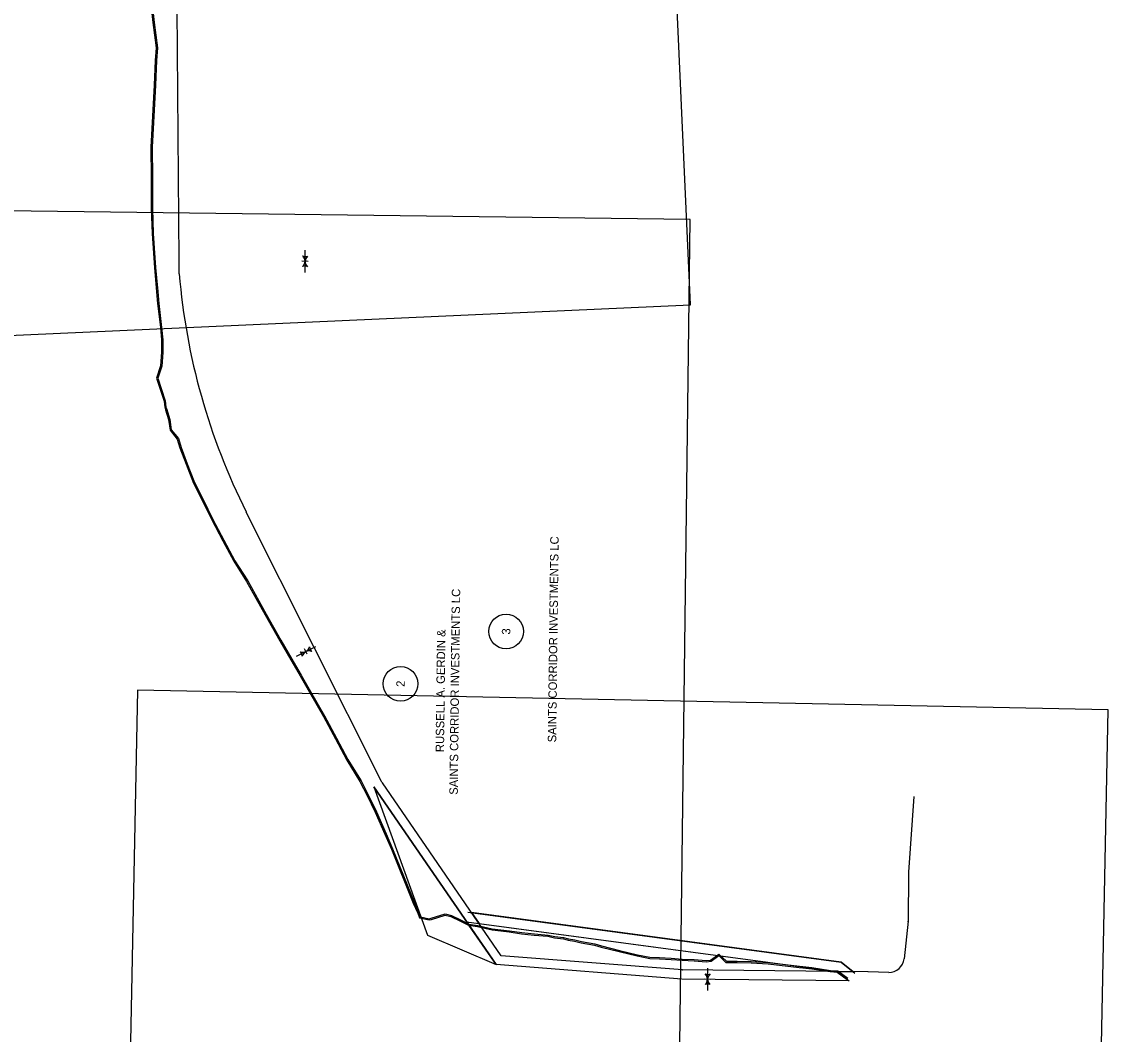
# Model space of a CAD drawing. Extents: x 20504422 to 20508365, y 7965199 to 7983597.
# Drawn here: x 20506611 to 20508365, y 7970508 to 7972142 of the extents above; entities that cross this region are included whole.
import ezdxf

# ---------------------------------------------------------------- set-up
doc = ezdxf.new("R2010")
doc.units = 0
for name, color, linetype in [('SurControl', 7, 'Continuous'), ('SurDikeDam', 7, 'Continuous'), ('SurHedge', 7, 'Continuous'), ('SurLotCorner', 7, 'Continuous'), ('SurRipRap', 7, 'Continuous'), ('SurTopOfWater', 7, 'Continuous'), ('SurTreeLineRight', 7, 'Continuous'), ('SurWetlands', 7, 'Continuous')]:
    doc.layers.add(name, color=color, linetype=linetype)

msp = doc.modelspace()

# ---------------------------------------------------------------- linework, layer by layer
at = {"layer": 'SurControl'}
for centre in [(20507392.5, 7971158.1), (20507222.2, 7971073.6)]:
    msp.add_circle(centre, 28, dxfattribs=at)
at = {"layer": 'SurDikeDam'}
for points in [[(20507179.2, 7970907.3), (20507265.7, 7970667.9), (20507376.4, 7970620.6)], [(20507336.9, 7970704.5), (20507348.9, 7970686.9), (20507927.3, 7970609.7), (20507927.3, 7970609.6), (20507952.3, 7970609.4), (20507933.4, 7970624.7)], [(20507328.9, 7970689.6), (20507927.3, 7970609.7), (20507946.2, 7970594.4), (20507676.2, 7970597.3), (20507376.4, 7970620.6)]]:
    msp.add_lwpolyline(points, close=True, dxfattribs=at)
at = {"layer": 'SurHedge'}
msp.add_lwpolyline([(20507336.9, 7970704.5), (20507348.9, 7970686.9), (20507927.3, 7970609.7), (20507927.3, 7970609.6), (20507952.3, 7970609.4), (20507933.4, 7970624.7)], close=True, dxfattribs=at)
at = {"layer": 'SurLotCorner'}
for p, q in [((20507068.1, 7971755.3), (20507068.3, 7971773.1)), ((20507073.1, 7971755.2), (20507063, 7971755.3)), ((20507068.1, 7971755.3), (20507067.9, 7971737.4)), ((20507069.5, 7971125.7), (20507053.5, 7971117.7)), ((20507071.7, 7971121.2), (20507067.2, 7971130.2)), ((20507069.5, 7971125.7), (20507085.4, 7971133.7)), ((20507717.8, 7970596.9), (20507718, 7970614.8)), ((20507722.8, 7970596.8), (20507712.7, 7970597)), ((20507717.8, 7970596.9), (20507717.5, 7970579))]:
    msp.add_line(p, q, dxfattribs=at)
for centre, radius, start, end in [((20507053.6, 7971757), 14.6, 315.366, 353.1732), ((20507053.6, 7971753.9), 14.6, 5.3849, 43.1922), ((20507068.3, 7971774.5), 11.4, 248.6722, 289.8859), ((20507082.6, 7971753.5), 14.6, 135.366, 173.1732), ((20507082.6, 7971756.6), 14.6, 185.3849, 223.1922), ((20507067.8, 7971736.1), 11.4, 68.6722, 109.8859), ((20507064.3, 7971139.3), 14.6, 252.7559, 290.5631), ((20507052.3, 7971117.1), 11.4, 6.0622, 47.2758), ((20507077.4, 7971113.4), 14.6, 122.7748, 160.5821), ((20507061.6, 7971138), 14.6, 302.7748, 340.5821), ((20507074.6, 7971112), 14.6, 72.7559, 110.5631), ((20507086.6, 7971134.3), 11.4, 186.0622, 227.2758), ((20507703.3, 7970598.6), 14.6, 315.366, 353.1732), ((20507703.2, 7970595.5), 14.6, 5.3849, 43.1922), ((20507718, 7970616.1), 11.4, 248.6722, 289.8859), ((20507732.3, 7970595.2), 14.6, 135.366, 173.1732), ((20507732.3, 7970598.3), 14.6, 185.3849, 223.1922), ((20507717.5, 7970577.7), 11.4, 68.6722, 109.8859)]:
    msp.add_arc(centre, radius, start, end, dxfattribs=at)
at = {"layer": 'SurRipRap'}
for points in [[(20505692.1, 7971595), (20507690.1, 7971685.2), (20507549.3, 7974806.4), (20505551.3, 7974716.3)], [(20505650.4, 7968713.3), (20507650.2, 7968688.1), (20507689.7, 7971822.9), (20505689.8, 7971848)]]:
    msp.add_lwpolyline(points, close=True, dxfattribs=at)
at = {"layer": 'SurTopOfWater'}
for points in [[(20506817.9, 7972179.4), (20506822.4, 7972140.4), (20506827.8, 7972099.9), (20506826.3, 7972079.5), (20506824.7, 7972039.5), (20506822.4, 7971999.5), (20506819.3, 7971939.7), (20506819.7, 7971889.8), (20506819.8, 7971839.9), (20506821.1, 7971800), (20506824.8, 7971745), (20506828.3, 7971706.2), (20506830, 7971687.1), (20506834.5, 7971648.4), (20506836.5, 7971628.7), (20506836.6, 7971608.5), (20506835, 7971586.4), (20506828.5, 7971566.5), (20506840.4, 7971529.7), (20506841.5, 7971519.9), (20506842.7, 7971515.6), (20506847.8, 7971499.9), (20506850.1, 7971482.6), (20506861.9, 7971468.3), (20506866.1, 7971454.4), (20506876, 7971428), (20506887.9, 7971397.6), (20506902.1, 7971369.9), (20506917.1, 7971339.1), (20506935.1, 7971304.5), (20506953.2, 7971271.3), (20506973.8, 7971238.7), (20507003.8, 7971184.8), (20507027.5, 7971142.8), (20507044.9, 7971112.4), (20507060.2, 7971086.4), (20507075.3, 7971060.3), (20507097.8, 7971020.9), (20507117, 7970985), (20507135.5, 7970950.3), (20507156.7, 7970916), (20507168.3, 7970893.5), (20507181.4, 7970866.3), (20507197, 7970831), (20507207.4, 7970806.6), (20507242.7, 7970719.5), (20507249.9, 7970703.5), (20507252.8, 7970696.1), (20507268.2, 7970692.6), (20507272.1, 7970693.6), (20507294.3, 7970700.3), (20507303.6, 7970698.1), (20507318.1, 7970691.1), (20507331.8, 7970684.1), (20507346.6, 7970681.9), (20507369.8, 7970676.5), (20507397.5, 7970673.3), (20507417.5, 7970670.5), (20507438, 7970668.1), (20507460, 7970666.3), (20507470.8, 7970664), (20507485, 7970662.4), (20507492.6, 7970660.1), (20507503.2, 7970658.5), (20507513.9, 7970655.9), (20507535.4, 7970652.1), (20507546.1, 7970649), (20507575.2, 7970641.5), (20507604.2, 7970634.7), (20507624.6, 7970630.5), (20507640.3, 7970629.8), (20507658.9, 7970628.9), (20507676.9, 7970627.6), (20507696.2, 7970626.8), (20507715.3, 7970625.1), (20507723.5, 7970625.9), (20507735.8, 7970635.1), (20507747.3, 7970623.9), (20507765.4, 7970624.2), (20507788, 7970623.4), (20507815.8, 7970622), (20507865.8, 7970615.9), (20507871.4, 7970615.4), (20507885.9, 7970614), (20507915.8, 7970609.3), (20507927.1, 7970608.5), (20507943.2, 7970596.8)], [(20506820, 7972179.2), (20506824.3, 7972140.7), (20506829.8, 7972099.9), (20506828.3, 7972079.4), (20506826.7, 7972039.4), (20506824.4, 7971999.4), (20506821.3, 7971939.7), (20506821.7, 7971889.9), (20506821.8, 7971839.9), (20506823.1, 7971800.1), (20506826.8, 7971745.1), (20506830.3, 7971706.4), (20506832, 7971687.3), (20506836.5, 7971648.6), (20506838.5, 7971628.8), (20506838.6, 7971608.4), (20506837, 7971586), (20506830.6, 7971566.5), (20506842.4, 7971530.1), (20506843.5, 7971520.2), (20506844.7, 7971516.2), (20506849.8, 7971500.3), (20506852, 7971483.5), (20506863.7, 7971469.3), (20506868, 7971455.1), (20506877.9, 7971428.7), (20506889.7, 7971398.5), (20506903.8, 7971370.8), (20506918.9, 7971340), (20506936.9, 7971305.4), (20506954.9, 7971272.3), (20506975.5, 7971239.7), (20507005.5, 7971185.8), (20507029.2, 7971143.8), (20507046.6, 7971113.4), (20507062, 7971087.4), (20507077.1, 7971061.3), (20507099.5, 7971021.9), (20507118.8, 7970985.9), (20507137.3, 7970951.3), (20507158.5, 7970917), (20507170.1, 7970894.4), (20507183.2, 7970867.2), (20507198.9, 7970831.8), (20507209.3, 7970807.3), (20507244.6, 7970720.3), (20507251.7, 7970704.3), (20507254.3, 7970697.8), (20507268.2, 7970694.6), (20507271.5, 7970695.5), (20507294.3, 7970702.4), (20507304.3, 7970700), (20507319, 7970692.9), (20507332.4, 7970686), (20507347, 7970683.8), (20507370.1, 7970678.4), (20507397.8, 7970675.3), (20507417.8, 7970672.5), (20507438.2, 7970670), (20507460.2, 7970668.3), (20507471.1, 7970666), (20507485.4, 7970664.4), (20507493.1, 7970662.1), (20507503.6, 7970660.4), (20507514.3, 7970657.9), (20507535.8, 7970654.1), (20507546.6, 7970650.9), (20507575.7, 7970643.5), (20507604.6, 7970636.6), (20507624.8, 7970632.5), (20507640.4, 7970631.8), (20507659.1, 7970630.9), (20507677, 7970629.6), (20507696.3, 7970628.8), (20507715.3, 7970627.1), (20507722.7, 7970627.9), (20507736, 7970637.7), (20507748.1, 7970625.9), (20507765.4, 7970626.2), (20507788.1, 7970625.4), (20507815.9, 7970624), (20507866, 7970617.9), (20507871.6, 7970617.4), (20507886.2, 7970616), (20507916.1, 7970611.3), (20507927.8, 7970610.5), (20507944.3, 7970598.5)], [(20507955.6, 7970606.1), (20507933.4, 7970624), (20507330.9, 7970704.4)]]:
    msp.add_lwpolyline(points, dxfattribs=at)
msp.add_lwpolyline([(20506797.8, 7971063.3), (20506777.7, 7970063.5), (20508344.4, 7970032), (20508364.5, 7971031.8)], close=True, dxfattribs=at)
at = {"layer": 'SurTreeLineRight'}
for p, q in [((20507191.4, 7970916.2), (20506973.2, 7971350.8)), ((20507192.1, 7970914.9), (20507191.4, 7970916.2)), ((20507192.8, 7970914), (20507192.1, 7970914.9)), ((20507384.7, 7970635), (20507192.8, 7970914))]:
    msp.add_line(p, q, dxfattribs=at)
for points in [[(20506865, 7971735.1), (20506864.9, 7971756.5), (20506864.9, 7971756.6), (20506860.4, 7972299.1), (20506860.4, 7972298.8), (20506865.4, 7972698.8), (20506865.4, 7972697.7), (20506900.4, 7973097.3), (20506900.4, 7973098.4), (20506901.2, 7973158.1), (20506901.2, 7973158), (20506901.8, 7973191.1), (20506901.8, 7973191.2), (20506902.2, 7973224.2), (20506903.1, 7973295.5)], [(20508050.7, 7970891.8), (20508042, 7970769.6), (20508042, 7970768.6), (20508041.5, 7970689.4), (20508041.6, 7970690.9), (20508035, 7970630)], [(20508010.1, 7970607.8), (20507976.7, 7970609.1), (20507976.3, 7970609.1), (20507676.3, 7970612.3), (20507677.3, 7970612.3), (20507384.7, 7970635)]]:
    msp.add_lwpolyline(points, dxfattribs=at)
for centre, radius, start, end in [((20507912.3, 7971822.7), 1051, 184.78, 206.6754), ((20508010.2, 7970632.8), 25, 269.7219, 353.6376)]:
    msp.add_arc(centre, radius, start, end, dxfattribs=at)
at = {"layer": 'SurWetlands'}
for p, q in [((20507179.2, 7970907.3), (20507376.4, 7970620.6)), ((20507336.9, 7970704.5), (20507933.4, 7970624.7)), ((20507328.9, 7970689.6), (20507927.3, 7970609.7)), ((20507933.4, 7970624.7), (20507952.3, 7970609.4)), ((20507927.3, 7970609.7), (20507946.2, 7970594.4))]:
    msp.add_line(p, q, dxfattribs=at)

# ---------------------------------------------------------------- texts
at = {"layer": 'SurControl'}
for s, p in [('SAINTS CORRIDOR INVESTMENTS LC', (20507473.4, 7970979.1)), ('SAINTS CORRIDOR INVESTMENTS LC', (20507314.5, 7970894.5)), ('RUSSELL A. GERDIN &', (20507292.3, 7970963.3)), ('3', (20507399.3, 7971153)), ('2', (20507228.9, 7971068.6))]:
    msp.add_text(s, height=13.6, rotation=89.2974, dxfattribs=at).set_placement(p)

doc.saveas('drawing.dxf')
